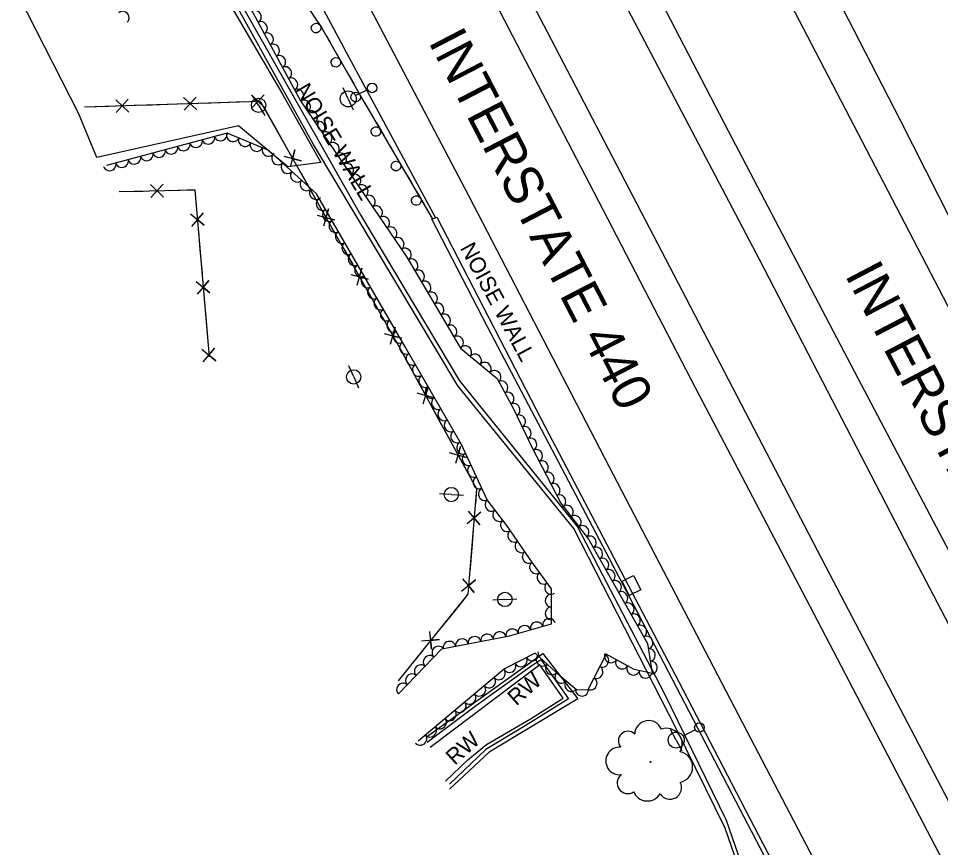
# Model space of a CAD drawing. Extents: x 1722896 to 1754269, y 648279 to 666297.
# Drawn here: x 1727579.8 to 1727868.1, y 654019.9 to 654279.2 of the extents above; entities that cross this region are included whole.
import ezdxf

# ---------------------------------------------------------------- set-up
doc = ezdxf.new("R2010")
doc.units = 0
for name, color, linetype in [('DESIGN - CENTERLINE - Proposed Text', 7, 'Continuous'), ('DESIGN - SCRATCH - User 1', 7, 'Continuous'), ('DESIGN - SHEET - Linework', 7, 'Continuous'), ('SURVEY - CENTERLINE - Preliminary', 7, 'Continuous'), ('SURVEY - CENTERLINE - Preliminary Text', 7, 'Continuous'), ('SURVEY - CONTOURS - Intermediate with optional Text', 7, 'Continuous'), ('SURVEY - DRAINAGE - Natural Features', 7, 'Continuous'), ('SURVEY - DTM - Breaklines', 7, 'Continuous'), ('SURVEY - VEGETATION - Features with Text', 7, 'Continuous')]:
    doc.layers.add(name, color=color, linetype=linetype)

msp = doc.modelspace()

# ---------------------------------------------------------------- linework, layer by layer
at = {"layer": 'DESIGN - CENTERLINE - Proposed Text'}
msp.add_lwpolyline([(1727707.39, 654054.58), (1727743.77, 654080.62), (1727754.69, 654066.42), (1727727.04, 654049.74), (1727714.61, 654038.16)], dxfattribs=at)
at = {"layer": 'DESIGN - SCRATCH - User 1'}
for points in [[(1727927.59, 653734.45), (1727926.17, 653733.65), (1727871.54, 653849.39), (1727850.91, 653896.35), (1727825.81, 653953.49), (1727800.77, 654025.96), (1727785.37, 654057.35), (1727753.48, 654119.66), (1727717.18, 654164.37), (1727672.06, 654239.76), (1727621.97, 654330.39)], [(1727622.54, 654331.36), (1727686.73, 654217.77), (1727717.7, 654165.84), (1727754.59, 654120.21), (1727781.55, 654068.35), (1727801.08, 654028.51), (1727824.69, 653960.51), (1727834.36, 653937.28), (1727857, 653885.22), (1727876.48, 653842.06), (1727927.37, 653734.57), (1727927.59, 653734.45)], [(1727656.65, 654302.96), (1727674.59, 654276.36), (1727687.94, 654253.03), (1727709.2, 654216.71)], [(1727672.84, 654278.96), (1727674.59, 654276.36), (1727675.32, 654275.09)], [(1727676.11, 654273.7), (1727677.28, 654271.66)], [(1727677.28, 654271.66), (1727678.45, 654269.62)], [(1727679.24, 654268.23), (1727681.52, 654264.24)], [(1727682.32, 654262.85), (1727683.49, 654260.81)], [(1727683.49, 654260.81), (1727684.65, 654258.77)], [(1727685.45, 654257.38), (1727687.73, 654253.39)], [(1727688.53, 654252.01), (1727689.72, 654249.98)], [(1727689.72, 654249.98), (1727690.91, 654247.95)], [(1727691.72, 654246.57), (1727694.04, 654242.6)], [(1727694.85, 654241.22), (1727696.04, 654239.19)], [(1727696.04, 654239.19), (1727697.22, 654237.16)], [(1727698.03, 654235.78), (1727700.35, 654231.81)], [(1727701.16, 654230.43), (1727702.35, 654228.4)], [(1727702.35, 654228.4), (1727703.54, 654226.38)], [(1727704.34, 654224.99), (1727706.67, 654221.03)], [(1727707.48, 654219.64), (1727708.66, 654217.62)], [(1727708.66, 654217.62), (1727709.2, 654216.71)], [(1727876, 653895.8), (1727842.83, 653960.05), (1727805.48, 654031.79), (1727770.93, 654098.16), (1727726.6, 654182.58), (1727709.1, 654216.44), (1727710.63, 654217.1), (1727743.28, 654153.86), (1727786.28, 654071.69), (1727827.8, 653991.85), (1727876.93, 653896.38), (1727876, 653895.8)], [(1727707.66, 654052.85), (1727723.05, 654064.47), (1727740.3, 654076.84), (1727743.19, 654078.73), (1727751.79, 654066.43), (1727737.71, 654057.67), (1727725.99, 654050.58), (1727714.61, 654039.68)], [(1727713.39, 654040.7), (1727720.32, 654047.32), (1727726.13, 654052.08), (1727739.87, 654060.15), (1727750.17, 654066.63), (1727742.84, 654077.03), (1727708.6, 654051.21)]]:
    msp.add_lwpolyline(points, dxfattribs=at)
for centre, start, end in [((1727672.87, 654276.24), 147.2673, 147.2575), ((1727679.07, 654265.51), 143.0186, 143.0087), ((1727685.27, 654254.66), 143.0186, 143.0087), ((1727691.57, 654243.85), 143.6036, 143.5938), ((1727697.89, 654233.06), 143.6036, 143.5938), ((1727704.2, 654222.27), 143.6036, 143.5938)]:
    msp.add_arc(centre, 1.5, start, end, dxfattribs=at)
at = {"layer": 'SURVEY - CENTERLINE - Preliminary'}
msp.add_lwpolyline([(1727612.89, 654338.81), (1727619.49, 654329.03), (1727662.34, 654255.54), (1727674.34, 654234.16), (1727664.05, 654232.84), (1727648.66, 654245.66), (1727604.39, 654235.79), (1727598.61, 654249.64), (1727582.65, 654280.92), (1727579.83, 654286.49), (1727612.89, 654338.81)], dxfattribs=at)
at = {"layer": 'SURVEY - CENTERLINE - Preliminary Text'}
for points in [[(1727732.21, 654484.49), (1727768.97, 654413.16), (1727813.96, 654328.14), (1727855.35, 654247.58), (1727944.04, 654072.45), (1727969.68, 654028.83), (1727996, 653978.27), (1728034.88, 653904.71), (1728077.58, 653821.81), (1728093.03, 653790.56)], [(1727722.77, 654472.46), (1727768.58, 654384.88), (1727826.36, 654273.79), (1727888.83, 654153.82), (1727943.15, 654050.35), (1728009.97, 653922.32), (1728073.7, 653799.5), (1728141.6, 653670.38), (1728151.37, 653652.53)], [(1728116.24, 653642.76), (1728107.48, 653658.71), (1728074.15, 653721.71), (1728046.24, 653775.34), (1728016.12, 653833.27), (1727981.9, 653898.85), (1727950.87, 653958.62), (1727914.73, 654028.82), (1727880.2, 654094.82), (1727841.31, 654168.57), (1727801.85, 654243.95), (1727765.71, 654313.53), (1727729.09, 654384.15), (1727699.55, 654441.02)], [(1728106.35, 653640.14), (1728099.8, 653652.14), (1728062.27, 653721.74), (1728019.66, 653803.94), (1727979.61, 653881.08), (1727952.11, 653934.01), (1727920.36, 653994.55), (1727860.06, 654109.98), (1727811.47, 654203.83), (1727757.76, 654306.23), (1727711.6, 654395.49), (1727693.17, 654431.8)], [(1727676.45, 654407.23), (1727702.23, 654357.01), (1727745.09, 654275.06), (1727787.23, 654194.22), (1727832.25, 654107.66), (1727872.91, 654030.02), (1727921.69, 653935.62), (1727972.69, 653838.18), (1728031.26, 653725.98), (1728066.56, 653657.62), (1728081.26, 653631.23)], [(1727670.06, 654398.14), (1727696.84, 654346.18), (1727726.41, 654289.12), (1727758.28, 654227.7), (1727791.37, 654163.81), (1727827.23, 654095.39), (1727871.21, 654011.12), (1727907.65, 653940.75), (1727947.57, 653864.69), (1727985.6, 653791.57), (1728021.79, 653722.61), (1728057.73, 653653.73), (1728071.86, 653627.42)], [(1728039.09, 653613.74), (1728031.22, 653628.09), (1727999.01, 653688.9), (1727962.52, 653758.75), (1727923.88, 653833.11), (1727884.58, 653908.28), (1727843.37, 653987.74), (1727806.26, 654058.8), (1727764.48, 654139.06), (1727720.61, 654223.76), (1727677.06, 654306.74), (1727646.13, 654366.33)], [(1727637.32, 654354.34), (1727659.52, 654311.28), (1727683.82, 654265.75), (1727710.26, 654216.86)]]:
    msp.add_lwpolyline(points, dxfattribs=at)
at = {"layer": 'SURVEY - DRAINAGE - Natural Features'}
msp.add_line((1727771.46, 654101.88), (1727771.46, 654101.88), dxfattribs=at)
msp.add_lwpolyline([(1727768.56, 654103.23), (1727772.15, 654105), (1727774.36, 654100.52), (1727770.78, 654098.75), (1727768.56, 654103.23)], dxfattribs=at)
at = {"layer": 'SURVEY - DTM - Breaklines'}
for p, q in [((1727682.92, 654254.08), (1727681.36, 654257.49)), ((1727689.06, 654256.89), (1727685.19, 654255.12)), ((1727654.91, 654252.07), (1727652.93, 654255.25)), ((1727682.92, 654254.08), (1727684.48, 654250.67)), ((1727654.91, 654252.07), (1727656.89, 654248.89)), ((1727684.64, 654167.11), (1727683.17, 654170.56)), ((1727684.64, 654167.11), (1727686.11, 654163.66)), ((1727715.17, 654130.32), (1727711.43, 654130.5)), ((1727715.17, 654130.32), (1727718.92, 654130.13)), ((1727731.91, 654097.5), (1727728.16, 654097.31)), ((1727731.91, 654097.5), (1727735.65, 654097.68)), ((1727785.47, 654053.51), (1727783.69, 654056.81)), ((1727791.41, 654056.72), (1727787.67, 654054.7)), ((1727785.47, 654053.51), (1727787.26, 654050.21))]:
    msp.add_line(p, q, dxfattribs=at)
for points in [[(1727610.36, 654249.82), (1727614.18, 654253.95), (1727612.3, 654251.88), (1727610.23, 654253.82), (1727614.31, 654249.95)], [(1727631.6, 654250.53), (1727635.42, 654254.66), (1727633.54, 654252.6), (1727631.47, 654254.53), (1727635.55, 654250.66)], [(1727652.84, 654251.24), (1727656.66, 654255.37), (1727654.77, 654253.31), (1727652.71, 654255.24), (1727656.79, 654251.38)], [(1727600.45, 654251.54), (1727655.42, 654253.38), (1727698.58, 654177.01), (1727723.07, 654132.05), (1727720.34, 654099.15), (1727698.56, 654072.06)], [(1727600.45, 654251.54), (1727607.95, 654251.79)], [(1727615.99, 654252.06), (1727621.69, 654252.25)], [(1727621.69, 654252.25), (1727629.19, 654252.5)], [(1727637.23, 654252.77), (1727642.93, 654252.96)], [(1727642.93, 654252.96), (1727650.42, 654253.21)], [(1727656.92, 654250.73), (1727659.73, 654245.76)], [(1727659.73, 654245.76), (1727663.42, 654239.23)], [(1727662.79, 654236.18), (1727668.21, 654234.71), (1727665.51, 654235.42), (1727666.27, 654238.15), (1727664.73, 654232.74)], [(1727667.38, 654232.23), (1727670.18, 654227.26)], [(1727611.28, 654225.07), (1727635, 654225.65), (1727639.44, 654173.36)], [(1727611.28, 654225.07), (1727618.78, 654225.25)], [(1727621.18, 654223.26), (1727625.03, 654227.36), (1727623.13, 654225.31), (1727621.08, 654227.26), (1727625.13, 654223.36)], [(1727626.83, 654225.45), (1727632.53, 654225.59)], [(1727632.53, 654225.59), (1727635, 654225.65), (1727635.43, 654220.64)], [(1727670.18, 654227.26), (1727673.87, 654220.73)], [(1727673.24, 654217.68), (1727678.67, 654216.21), (1727675.97, 654216.92), (1727676.72, 654219.65), (1727675.18, 654214.24)], [(1727633.58, 654218.13), (1727637.9, 654214.53), (1727635.74, 654216.31), (1727637.57, 654218.47), (1727633.92, 654214.19)], [(1727677.83, 654213.72), (1727680.63, 654208.76)], [(1727636.11, 654212.62), (1727636.59, 654206.95)], [(1727680.63, 654208.76), (1727684.32, 654202.23)], [(1727636.59, 654206.95), (1727637.22, 654199.47)], [(1727683.7, 654199.18), (1727689.12, 654197.71), (1727686.42, 654198.42), (1727687.18, 654201.15), (1727685.64, 654195.74)], [(1727635.38, 654196.96), (1727639.7, 654193.36), (1727637.54, 654195.14), (1727639.36, 654197.3), (1727635.71, 654193.02)], [(1727688.28, 654195.22), (1727691.09, 654190.26)], [(1727637.9, 654191.45), (1727638.39, 654185.78)], [(1727691.09, 654190.26), (1727694.78, 654183.73)], [(1727638.39, 654185.78), (1727639.02, 654178.3)], [(1727694.15, 654180.68), (1727699.57, 654179.21), (1727696.87, 654179.92), (1727697.63, 654182.65), (1727696.09, 654177.24)], [(1727637.18, 654175.79), (1727641.5, 654172.19), (1727639.34, 654173.96), (1727641.16, 654176.13), (1727637.51, 654171.85)], [(1727698.73, 654176.72), (1727701.46, 654171.72)], [(1727701.46, 654171.72), (1727705.04, 654165.14)], [(1727704.37, 654162.09), (1727709.77, 654160.54), (1727707.08, 654161.29), (1727707.88, 654164.01), (1727706.26, 654158.63)], [(1727708.89, 654158.07), (1727711.62, 654153.07)], [(1727711.62, 654153.07), (1727715.21, 654146.48)], [(1727714.53, 654143.44), (1727719.93, 654141.89), (1727717.24, 654142.64), (1727718.04, 654145.35), (1727716.42, 654139.98)], [(1727719.05, 654139.42), (1727721.78, 654134.42)], [(1727721.78, 654134.42), (1727723.07, 654132.05), (1727722.68, 654127.27)], [(1727720.44, 654125.1), (1727724.1, 654120.83), (1727722.27, 654122.94), (1727724.42, 654124.77), (1727720.11, 654121.17)], [(1727722.01, 654119.25), (1727721.54, 654113.58)], [(1727721.54, 654113.58), (1727720.92, 654106.11)], [(1727718.68, 654103.94), (1727722.34, 654099.68), (1727720.51, 654101.78), (1727722.67, 654103.61), (1727718.35, 654100.01)], [(1727719.68, 654098.32), (1727716.11, 654093.88)], [(1727716.11, 654093.88), (1727711.41, 654088.04)], [(1727708.34, 654087.49), (1727708.98, 654081.91), (1727708.64, 654084.68), (1727711.46, 654084.98), (1727705.86, 654084.41)], [(1727706.36, 654081.76), (1727702.79, 654077.32)], [(1727702.79, 654077.32), (1727698.56, 654072.06)]]:
    msp.add_lwpolyline(points, dxfattribs=at)
for centre, radius in [((1727682.92, 654254.08), 2.5), ((1727690.42, 654257.51), 1.5), ((1727654.91, 654252.07), 2.25), ((1727684.64, 654167.11), 2.25), ((1727715.17, 654130.32), 2.25), ((1727731.91, 654097.5), 2.25), ((1727792.73, 654057.44), 1.5), ((1727785.47, 654053.51), 2.5)]:
    msp.add_circle(centre, radius, dxfattribs=at)
at = {"layer": 'SURVEY - VEGETATION - Features with Text'}
for points in [[(1727620.44, 654331.82), (1727639.55, 654306.32), (1727668, 654253.51), (1727701.3, 654204.59), (1727718.06, 654176.14), (1727729.46, 654166.58), (1727734.69, 654156.89), (1727740.47, 654144.96), (1727749.36, 654127.63), (1727758.01, 654116.35), (1727776.45, 654083.72), (1727777.95, 654074.34), (1727772.29, 654075.58), (1727763.54, 654080.4), (1727757.81, 654069.22), (1727754.36, 654069.14), (1727749.06, 654073.59), (1727741.42, 654080.65), (1727731.8, 654075.75), (1727704.78, 654053.2)], [(1727698.61, 654067.94), (1727712.2, 654082.06), (1727733.3, 654086.1), (1727746.43, 654089.84), (1727746.43, 654100.84), (1727740.49, 654108.99), (1727732.5, 654120.65), (1727726.38, 654128.67), (1727718.32, 654145.92), (1727700.76, 654176.49), (1727672.97, 654224.39), (1727658.15, 654237.94), (1727645.05, 654243.39), (1727607.39, 654233.22)]]:
    msp.add_lwpolyline(points, dxfattribs=at)
msp.add_circle((1727777.47, 654046.67), 0.151, dxfattribs=at)
for centre, radius, start, end in [((1727776.83, 654055.3), 4.33, 22.0721, 178.8611), ((1727770.37, 654053.31), 2.97, 44.1883, 222.9339), ((1727782.42, 654052.26), 4.93, 331.1249, 108.6491), ((1727767.76, 654046.99), 4.32, 84.209, 277.6287), ((1727785.71, 654045.09), 4.9, 282.0207, 77.8592), ((1727770.3, 654040.07), 3.29, 126.8277, 304.1468), ((1727783.51, 654038.63), 3.62, 212.2736, 27.2739), ((1727776.46, 654039.11), 4.66, 202.1147, 328.9604)]:
    msp.add_arc(centre, radius, start, end, dxfattribs=at)
for centre, major_axis in [((1727612.51, 654279.53), (1.31, -1.51)), ((1727653.84, 654279.79), (0.95, -1.76)), ((1727655.74, 654276.27), (0.95, -1.76)), ((1727657.63, 654272.75), (0.95, -1.76)), ((1727659.53, 654269.22), (0.95, -1.76)), ((1727661.43, 654265.7), (0.95, -1.76)), ((1727663.33, 654262.18), (0.95, -1.76)), ((1727665.22, 654258.66), (0.95, -1.76)), ((1727667.12, 654255.14), (0.95, -1.76)), ((1727669.21, 654251.73), (1.13, -1.65)), ((1727671.46, 654248.43), (1.13, -1.65)), ((1727673.71, 654245.12), (1.13, -1.65)), ((1727639.24, 654241.82), (-1.93, -0.52)), ((1727643.1, 654242.86), (-1.93, -0.52)), ((1727646.88, 654242.63), (-1.85, 0.77)), ((1727675.96, 654241.81), (1.13, -1.65)), ((1727627.65, 654238.69), (-1.93, -0.52)), ((1727631.51, 654239.73), (-1.93, -0.52)), ((1727635.38, 654240.77), (-1.93, -0.52)), ((1727650.57, 654241.09), (-1.85, 0.77)), ((1727654.26, 654239.55), (-1.85, 0.77)), ((1727678.21, 654238.51), (1.13, -1.65)), ((1727619.93, 654236.61), (-1.93, -0.52)), ((1727623.79, 654237.65), (-1.93, -0.52)), ((1727657.96, 654238.02), (-1.85, 0.77)), ((1727660.95, 654235.38), (-1.48, 1.35)), ((1727680.46, 654235.2), (1.13, -1.65)), ((1727608.34, 654233.48), (-1.93, -0.52)), ((1727612.2, 654234.52), (-1.93, -0.52)), ((1727616.07, 654235.56), (-1.93, -0.52)), ((1727663.9, 654232.68), (-1.48, 1.35)), ((1727682.71, 654231.89), (1.13, -1.65)), ((1727666.85, 654229.98), (-1.48, 1.35)), ((1727684.96, 654228.59), (1.13, -1.65)), ((1727669.8, 654227.28), (-1.48, 1.35)), ((1727672.76, 654224.58), (-1.48, 1.35)), ((1727687.21, 654225.28), (1.13, -1.65)), ((1727674.83, 654221.18), (-1, 1.73)), ((1727689.46, 654221.97), (1.13, -1.65)), ((1727676.84, 654217.72), (-1, 1.73)), ((1727691.71, 654218.66), (1.13, -1.65)), ((1727693.96, 654215.36), (1.13, -1.65)), ((1727678.85, 654214.26), (-1, 1.73)), ((1727696.22, 654212.05), (1.13, -1.65)), ((1727680.85, 654210.8), (-1, 1.73)), ((1727698.47, 654208.74), (1.13, -1.65)), ((1727682.86, 654207.34), (-1, 1.73)), ((1727700.72, 654205.44), (1.13, -1.65)), ((1727684.87, 654203.88), (-1, 1.73)), ((1727686.87, 654200.42), (-1, 1.73)), ((1727702.8, 654202.03), (1.02, -1.72)), ((1727704.84, 654198.58), (1.02, -1.72)), ((1727688.88, 654196.96), (-1, 1.73)), ((1727706.87, 654195.14), (1.02, -1.72)), ((1727690.89, 654193.5), (-1, 1.73)), ((1727708.9, 654191.69), (1.02, -1.72)), ((1727692.9, 654190.04), (-1, 1.73)), ((1727710.93, 654188.24), (1.02, -1.72)), ((1727694.9, 654186.58), (-1, 1.73)), ((1727696.91, 654183.12), (-1, 1.73)), ((1727712.96, 654184.8), (1.02, -1.72)), ((1727714.99, 654181.35), (1.02, -1.72)), ((1727698.92, 654179.66), (-1, 1.73)), ((1727717.02, 654177.91), (1.02, -1.72)), ((1727700.92, 654176.2), (-1, 1.73)), ((1727719.55, 654174.89), (1.53, -1.29)), ((1727702.92, 654172.73), (-1, 1.73)), ((1727722.62, 654172.32), (1.53, -1.29)), ((1727704.91, 654169.26), (-1, 1.73)), ((1727725.68, 654169.74), (1.53, -1.29)), ((1727706.9, 654165.79), (-1, 1.73)), ((1727728.75, 654167.17), (1.53, -1.29)), ((1727730.92, 654163.88), (0.95, -1.76)), ((1727708.9, 654162.33), (-1, 1.73)), ((1727732.82, 654160.35), (0.95, -1.76)), ((1727710.89, 654158.86), (-1, 1.73)), ((1727734.72, 654156.83), (0.87, -1.8)), ((1727712.88, 654155.39), (-1, 1.73)), ((1727714.87, 654151.92), (-1, 1.73)), ((1727736.46, 654153.23), (0.87, -1.8)), ((1727716.87, 654148.45), (-1, 1.73)), ((1727738.2, 654149.63), (0.87, -1.8)), ((1727739.95, 654146.03), (0.87, -1.8)), ((1727718.78, 654144.94), (-0.85, 1.81)), ((1727741.75, 654142.46), (0.91, -1.78)), ((1727720.47, 654141.32), (-0.85, 1.81)), ((1727722.16, 654137.69), (-0.85, 1.81)), ((1727743.58, 654138.9), (0.91, -1.78)), ((1727723.86, 654134.07), (-0.85, 1.81)), ((1727745.4, 654135.34), (0.91, -1.78)), ((1727747.23, 654131.79), (0.91, -1.78)), ((1727725.55, 654130.45), (-0.85, 1.81)), ((1727749.05, 654128.23), (0.91, -1.78)), ((1727727.62, 654127.05), (-1.21, 1.59)), ((1727751.38, 654124.99), (1.22, -1.59)), ((1727730.05, 654123.87), (-1.21, 1.59)), ((1727753.82, 654121.81), (1.22, -1.59)), ((1727732.47, 654120.69), (-1.21, 1.59)), ((1727734.74, 654117.39), (-1.13, 1.65)), ((1727756.25, 654118.64), (1.22, -1.59)), ((1727737, 654114.09), (-1.13, 1.65)), ((1727758.56, 654115.38), (0.98, -1.74)), ((1727739.26, 654110.79), (-1.13, 1.65)), ((1727760.53, 654111.9), (0.98, -1.74)), ((1727762.49, 654108.42), (0.98, -1.74)), ((1727741.56, 654107.52), (-1.18, 1.62)), ((1727764.46, 654104.93), (0.98, -1.74)), ((1727743.92, 654104.29), (-1.18, 1.62)), ((1727746.27, 654101.06), (-1.18, 1.62)), ((1727766.43, 654101.45), (0.98, -1.74)), ((1727746.43, 654097.11), (0, 2)), ((1727768.4, 654097.97), (0.98, -1.74)), ((1727746.43, 654093.11), (0, 2)), ((1727770.37, 654094.49), (0.98, -1.74)), ((1727772.34, 654091), (0.98, -1.74)), ((1727738.03, 654087.44), (1.92, 0.55)), ((1727741.88, 654088.54), (1.92, 0.55)), ((1727745.73, 654089.64), (1.92, 0.55)), ((1727774.3, 654087.52), (0.98, -1.74)), ((1727726.35, 654084.76), (1.96, 0.38)), ((1727730.28, 654085.52), (1.96, 0.38)), ((1727734.19, 654086.35), (1.92, 0.55)), ((1727714.56, 654082.51), (1.96, 0.38)), ((1727718.49, 654083.26), (1.96, 0.38)), ((1727722.42, 654084.01), (1.96, 0.38)), ((1727776.27, 654084.04), (0.98, -1.74)), ((1727711.09, 654080.91), (1.39, 1.44)), ((1727740.52, 654080.19), (-1.78, -0.91)), ((1727777.03, 654080.13), (0.32, -1.97)), ((1727708.32, 654078.02), (1.39, 1.44)), ((1727736.95, 654078.37), (-1.78, -0.91)), ((1727743.61, 654078.62), (-1.47, 1.36)), ((1727762.47, 654078.31), (-0.91, -1.78)), ((1727764.99, 654079.6), (-1.75, 0.96)), ((1727768.5, 654077.67), (-1.75, 0.96)), ((1727777.66, 654076.18), (0.32, -1.97)), ((1727705.54, 654075.14), (1.39, 1.44)), ((1727730.1, 654074.33), (-1.54, -1.28)), ((1727733.39, 654076.56), (-1.78, -0.91)), ((1727746.55, 654075.9), (-1.47, 1.36)), ((1727760.65, 654074.75), (-0.91, -1.78)), ((1727772, 654075.75), (-1.75, 0.96)), ((1727775.87, 654074.8), (-1.95, 0.43)), ((1727702.77, 654072.26), (1.39, 1.44)), ((1727727.03, 654071.77), (-1.54, -1.28)), ((1727749.51, 654073.21), (-1.53, 1.29)), ((1727758.82, 654071.19), (-0.91, -1.78)), ((1727700, 654069.38), (1.39, 1.44)), ((1727723.96, 654069.2), (-1.54, -1.28)), ((1727752.58, 654070.64), (-1.53, 1.29)), ((1727756.03, 654069.18), (-2, -0.05)), ((1727720.89, 654066.64), (-1.54, -1.28)), ((1727717.82, 654064.08), (-1.54, -1.28)), ((1727714.74, 654061.51), (-1.54, -1.28)), ((1727708.6, 654056.39), (-1.54, -1.28)), ((1727711.67, 654058.95), (-1.54, -1.28)), ((1727705.53, 654053.83), (-1.54, -1.28))]:
    msp.add_ellipse(centre, major_axis=major_axis, ratio=0.940188, start_param=0, end_param=3.141593, dxfattribs=at)

# ---------------------------------------------------------------- texts
at = {"layer": 'DESIGN - SCRATCH - User 1'}
for rotation, p in [(300.6296, (1727666.29, 654257.08)), (298.306, (1727717.75, 654207.44))]:
    msp.add_text('NOISE WALL', height=5, rotation=rotation, dxfattribs=at).set_placement(p)
at = {"layer": 'DESIGN - SHEET - Linework'}
for rotation, p in [(297.3824, (1727707.81, 654272.03)), (297.6279, (1727838.05, 654199.09))]:
    msp.add_text('INTERSTATE 440', height=12, rotation=rotation, dxfattribs=at).set_placement(p)
at = {"layer": 'SURVEY - CONTOURS - Intermediate with optional Text'}
for rotation, p in [(41.8377, (1727735.49, 654064.02)), (42.4103, (1727716.25, 654045.42))]:
    msp.add_text('RW', height=5, rotation=rotation, dxfattribs=at).set_placement(p)

doc.saveas('drawing.dxf')
